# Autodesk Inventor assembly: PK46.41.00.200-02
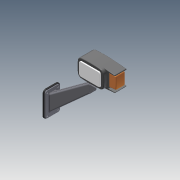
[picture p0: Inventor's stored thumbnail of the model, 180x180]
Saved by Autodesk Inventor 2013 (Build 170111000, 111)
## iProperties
Created: 2005-07
Part Number: PK46.41.00.200-02
Document SubType Name: Assembly
Designer: tedescj
Manufacturer: Standard
Standards Organization: Custom
Author: PVitaliy
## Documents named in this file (11)
- D:\FrontLoaderVault\Data\Assy, Chassis, Front\PK46.41.00.200-02.iam
- D:\FrontLoaderVault\Data\Assy, Chassis, Front\05.483.000-02.ipt
- D:\FrontLoaderVault\Data\Assy, Chassis, Front\D395A-0401269-01.ipt
- D:\FrontLoaderVault\Data\Assy, Chassis, Front\PK46.41.00.210-02.iam
- D:\FrontLoaderVault\Data\Assy, Chassis, Rear\10.65G.019.ipt
- D:\FrontLoaderVault\Data\Assy, Chassis, Rear\M10-6H.5.019(S16).ipt
- D:\FrontLoaderVault\Data\Assy, Chassis, Front\D395A-0401270.ipt
- D:\FrontLoaderVault\Data\Assy, Chassis, Front\PK46.41.00.012A.ipt
- 10.65G.019.ipt
- M10-6H.5.019(S16).ipt
- PK46.41.00.012A.ipt
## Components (7 placed, 7 different names)
1. 05.483.000-02:1 — Вставка:1
2. D395A-0401269-01:1 — Вставка:6
3. PK46.41.00.210-02:1 [sub-assembly] — Вставка:6, Вставка:1, Insert:9, Insert:11, Insert:8, Insert:7
4. 10.65G.019:1 — Insert:9, Insert:10
5. M10-6H.5.019(S16):1 — Insert:10
6. D395A-0401270:1 — Insert:11
7. PK46.41.00.012A:1 — Insert:8, Insert:7
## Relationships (7: Insert 7)
- Вставка:6 [Insert]: D395A-0401269-01:1 ↔ PK46.41.00.210-02:1
- Вставка:1 [Insert]: 05.483.000-02:1 ↔ PK46.41.00.210-02:1
- Insert:9: PK46.41.00.210-02:1 ↔ 10.65G.019:1
- Insert:10: 10.65G.019:1 ↔ M10-6H.5.019(S16):1
- Insert:11: PK46.41.00.210-02:1 ↔ D395A-0401270:1
- Insert:8: PK46.41.00.210-02:1 ↔ PK46.41.00.012A:1
- Insert:7: PK46.41.00.210-02:1 ↔ PK46.41.00.012A:1
